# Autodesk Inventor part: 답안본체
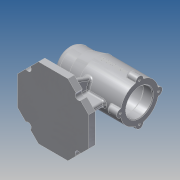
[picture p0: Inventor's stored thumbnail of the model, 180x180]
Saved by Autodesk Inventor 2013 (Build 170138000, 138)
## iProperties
Created: 2019-12
Part Number: 답안본체
Material: 알루미늄 6061
Document SubType Name: Modeling
Designer: Administrator
Density: 2.71 g/cm^3
Mass: 728.497 g
Surface Area: 714.692 cm^2
Volume: 268.818 cm^3
Author: Administrator
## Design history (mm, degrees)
sketch "스케치1"
  geometry: L1 (0, 0)-(112, 0); L2 (112, 0)-(112, 30); L3 (112, 30)-(45, 30); L4 (45, 30)-(25, 25); L5 (25, 25)-(0, 25); L6 (0, 25)-(0, 0)
  constraints: 12 end point, 2 parallel, 2 perpendicular, 1 horizontal
  dimensions: "d0" = 112 distance of L1.start L1.end; "d2" = 60 diameter of L3 L1; "d3" = 50 diameter of L5 L1; "d4" = 25 distance of L4.end L5.end; "d5" = 45 horizontal distance of L5.end L3.end
revolve "회전1" sketch "스케치1" stored, may be unused: angle "d6" = 90 deg
node "작업 평면1"
sketch "스케치2"
  geometry: L1 (-112, 30)-(-112, -30) reference; L2 (0, 25)-(0, -25) reference; L3 (0, -56)-(-112, -56); L4 (-112, -56)-(-112, 56); L5 (-112, 56)-(0, 56); L6 (0, 56)-(0, -56); 3 further points
  constraints: 8 end point, 2 midpoint, 2 parallel, 2 point on line, 1 coincident, 1 horizontal, 1 perpendicular
  dimensions: "d8" = 112 distance of L5.end L3.start
extrude "돌출1" join sketch "스케치2" distance "d10" = 10; taper "d11" = 0 deg
sketch "스케치3"
  geometry: L1 (0, -56)-(112, -56) reference; L2 (112, -56)-(112, 56) reference; L3 (112, 56)-(112, -56) reference; L4 (112, -56)-(0, -56) reference; L5 (0, -56)-(0, 56) reference; L6 (0, 56)-(112, 56) reference; L7 (56, 0)-(112, 56); L8 (95.598, 39.598)-(118.782, 16.414); L9 (118.782, 16.414)-(66.566, 68.63); L10 (66.566, 68.63)-(127.601, 68.63); L11 (127.601, 68.63)-(127.601, 16.414); L12 (127.601, 16.414)-(118.782, 16.414); C1 r 5 at (95.598, 39.598); 3 further points
  constraints: 12 end point, 2 midpoint, 2 parallel, 2 perpendicular, 1 centre point, 1 collinear, 1 horizontal alignment, 1 point on line, 1 vertical alignment, 4 other
  dimensions: "d12" = 10 diameter of C1
extrude "돌출2" cut sketch "스케치3" distance "d13" = 10; taper "d14" = 0 deg
sketch "스케치4"
  geometry: L1 (112, 23.196)-(79.196, 56) reference; C1 r 5 at (95.598, 39.598); 1 further point
  constraints: 1 centre point, 1 midpoint
  dimensions: "d15" = 10 diameter of C1
extrude "돌출3" cut sketch "스케치4" distance "d16" = 10; taper "d17" = 0 deg
node "작업 평면2"
node "작업 평면3"
sketch "스케치5"
  geometry: L1 (-79.196, 10)-(32.804, 10) reference; L2 (32.804, 10)-(32.804, 0) reference; L3 (32.804, 0)-(-79.196, 0) reference; L4 (-79.196, 0)-(-79.196, 10) reference; L5 (-59.196, 10)-(-42.174, 56.766); L6 (-42.174, 56.766)-(-23.196, 56.766); L7 (-23.196, 56.766)-(-23.196, 10); L8 (-59.196, 10)-(-23.196, 10); 2 further points
  constraints: 8 end point, 1 midpoint, 1 parallel, 1 perpendicular, 1 point on line, 2 other
  dimensions: "d19" = 20 distance of L5.start L1.start; "d20" = 110 deg angle of L5 L1
extrude "돌출4" join sketch "스케치5" stored distance "d21" = 8; taper "d22" = 0 deg
node "작업 평면4"
sketch "스케치6"
  geometry: L1 (-79.196, 55)-(-79.196, 105) reference; L2 (-79.196, 105)-(-54.196, 105) reference; L3 (-54.196, 105)-(-34.196, 110) reference; L4 (-34.196, 110)-(32.804, 110) reference; L5 (32.804, 110)-(32.804, 50) reference; L6 (32.804, 50)-(-19.196, 50) reference; L7 (-19.196, 50)-(-19.196, 10) reference; L8 (-19.196, 10)-(32.804, 10) reference; L9 (32.804, 10)-(32.804, 0) reference; L10 (32.804, 0)-(-79.196, 0) reference; L11 (-79.196, 0)-(-79.196, 10) reference; L12 (-79.196, 10)-(-27.196, 10) reference; L13 (-27.196, 10)-(-27.196, 50) reference; L14 (-27.196, 50)-(-34.196, 50) reference; L15 (-34.196, 50)-(-54.196, 55) reference; L16 (-54.196, 55)-(-79.196, 55) reference; L17 (-61.196, 10)-(-39.775, 55.937); L18 (7.804, 10)-(7.804, 61.764); L19 (-39.775, 55.937)-(7.804, 61.764); L20 (-61.196, 10)-(7.804, 10); 1 further point
  constraints: 8 end point, 2 point on line, 1 collinear, 1 perpendicular
  dimensions: "d24" = 115 deg angle of L17 L12; "d25" = 18 distance of L11.end L17.start; "d26" = 25 distance of L8.end L18.start
extrude "돌출5" join sketch "스케치6" stored distance "d27" = 8; taper "d28" = 0 deg
sketch "스케치7"
  geometry: L1 (0, -25)-(0, 25) reference; L2 (0, 25)-(25, 25) reference; L3 (25, 25)-(45, 30) reference; L4 (45, 30)-(112, 30) reference; L5 (112, 30)-(112, -30) reference; L6 (112, -30)-(87, -30) reference; L7 (87, -30)-(87, -70) reference; L8 (87, -70)-(112, -70) reference; L9 (112, -70)-(112, -80) reference; L10 (112, -80)-(0, -80) reference; L11 (0, -80)-(0, -70) reference; L12 (0, -70)-(18, -70) reference; L13 (18, -70)-(37.524, -28.131) reference; L14 (37.524, -28.131)-(25, -25) reference; L15 (25, -25)-(0, -25) reference; L16 (112, 0)-(6, 0); L17 (112, 0)-(112, 21); L18 (112, 21)-(97, 21); L19 (97, 21)-(97, 24); L20 (97, 24)-(43, 24); L21 (43, 24)-(43, 21); L22 (43, 21)-(31, 21); L23 (31, 21)-(31, 17.5); L24 (31, 17.5)-(13, 17.5); L25 (13, 17.5)-(13, 16); L26 (13, 16)-(9, 16); L27 (9, 16)-(9, 10.5); L28 (9, 10.5)-(6, 10.5); L29 (6, 10.5)-(6, 0); 1 further point
  constraints: 28 end point, 7 parallel, 6 perpendicular, 1 midpoint, 1 point on line
  dimensions: "d29" = 106 distance of L16.start L16.end; "d30" = 21 distance of L16.start L17.end; "d31" = 15 distance of L17.end L18.end; "d32" = 48 diameter of L20 L16; "d33" = 42 diameter of L22 L16; "d34" = 35 diameter of L24 L16; "d35" = 32 diameter of L26 L16; "d36" = 21 diameter of L28 L16; "d37" = 3 distance of L27.end L28.end; "d38" = 4 distance of L25.end L26.end; "d39" = 18 distance of L23.end L24.end; "d40" = 12 distance of L21.end L22.end
revolve "회전2" sketch "스케치7" stored, may be unused: angle "d41" = 90 deg
fillet "모깎기1" dims "d42" = 10
fillet "모깎기2" dims "d43" = 3
sketch "스케치8"
  geometry: C1 r 6 at (0, 30); 1 further point
  constraints: 1 centre point, 1 vertical alignment, 1 other
  dimensions: "d44" = 12 diameter of C1
extrude "돌출6" join sketch "스케치8" distance "d45" = 16; taper "d46" = 0 deg
fillet "모깎기3" dims "d47" = 3
fillet "모깎기4" dims "d48" = 1
sketch "스케치9"
  geometry: A1 r 6 centre (0, 0) between (5.998, 0.171) and (-5.998, 0.171) reference
hole "구멍1" sketch "스케치9" at (0, 0) diameter "d52" = 3.242; stored, may be unused: countersink angle "d56" = 90 deg, drill point angle "d58" = 118 deg; dims "d53" = 8, "d54" = 4, "d55" = 2, "d57" = 11
chamfer "모따기1" distance "d62" = 1; stored, may be unused: second distance "d63" = 2, angle "d64" = 45 deg
fillet "모깎기5" dims "d65" = 3
fillet "모깎기6" dims "d66" = 0.3
fillet "모깎기7" dims "d67" = 3
fillet "모깎기8" dims "d68" = 3
fillet "모깎기9" dims "d69" = 3
node "작업 평면5"
sketch "스케치10"
  geometry: L1 (112, 6.771)-(112, 29.226) reference; 2 further points
  constraints: 1 horizontal alignment, 1 other
  dimensions: "d71" = 41 distance from line of L1 point (71, 0)
feature "엠보싱1" sketch "스케치10" dims "d72" = 0.5, "d73" = 0
node "솔리드1"
mirror "대칭1"
mirror "대칭2"
mirror "대칭3"
pattern_circular "원형 패턴1" dims "d50" = 360 deg
pattern_circular "원형 패턴2" dims angle "d60" = 360 deg
node "절단 모서리 투영1"
node "절단 모서리 투영2"
node "절단 모서리 투영3"
node "절단 모서리 투영4"
other parameters: "d18" = -56, "d23" = -56, "d70" = 37
